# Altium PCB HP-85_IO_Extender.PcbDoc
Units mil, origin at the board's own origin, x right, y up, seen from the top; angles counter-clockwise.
Board outline 3937.01 x 3937.01 mil, 2 copper layers (Top Layer, Bottom Layer); 44 components, 33 nets, 145 pads, 56 vias.
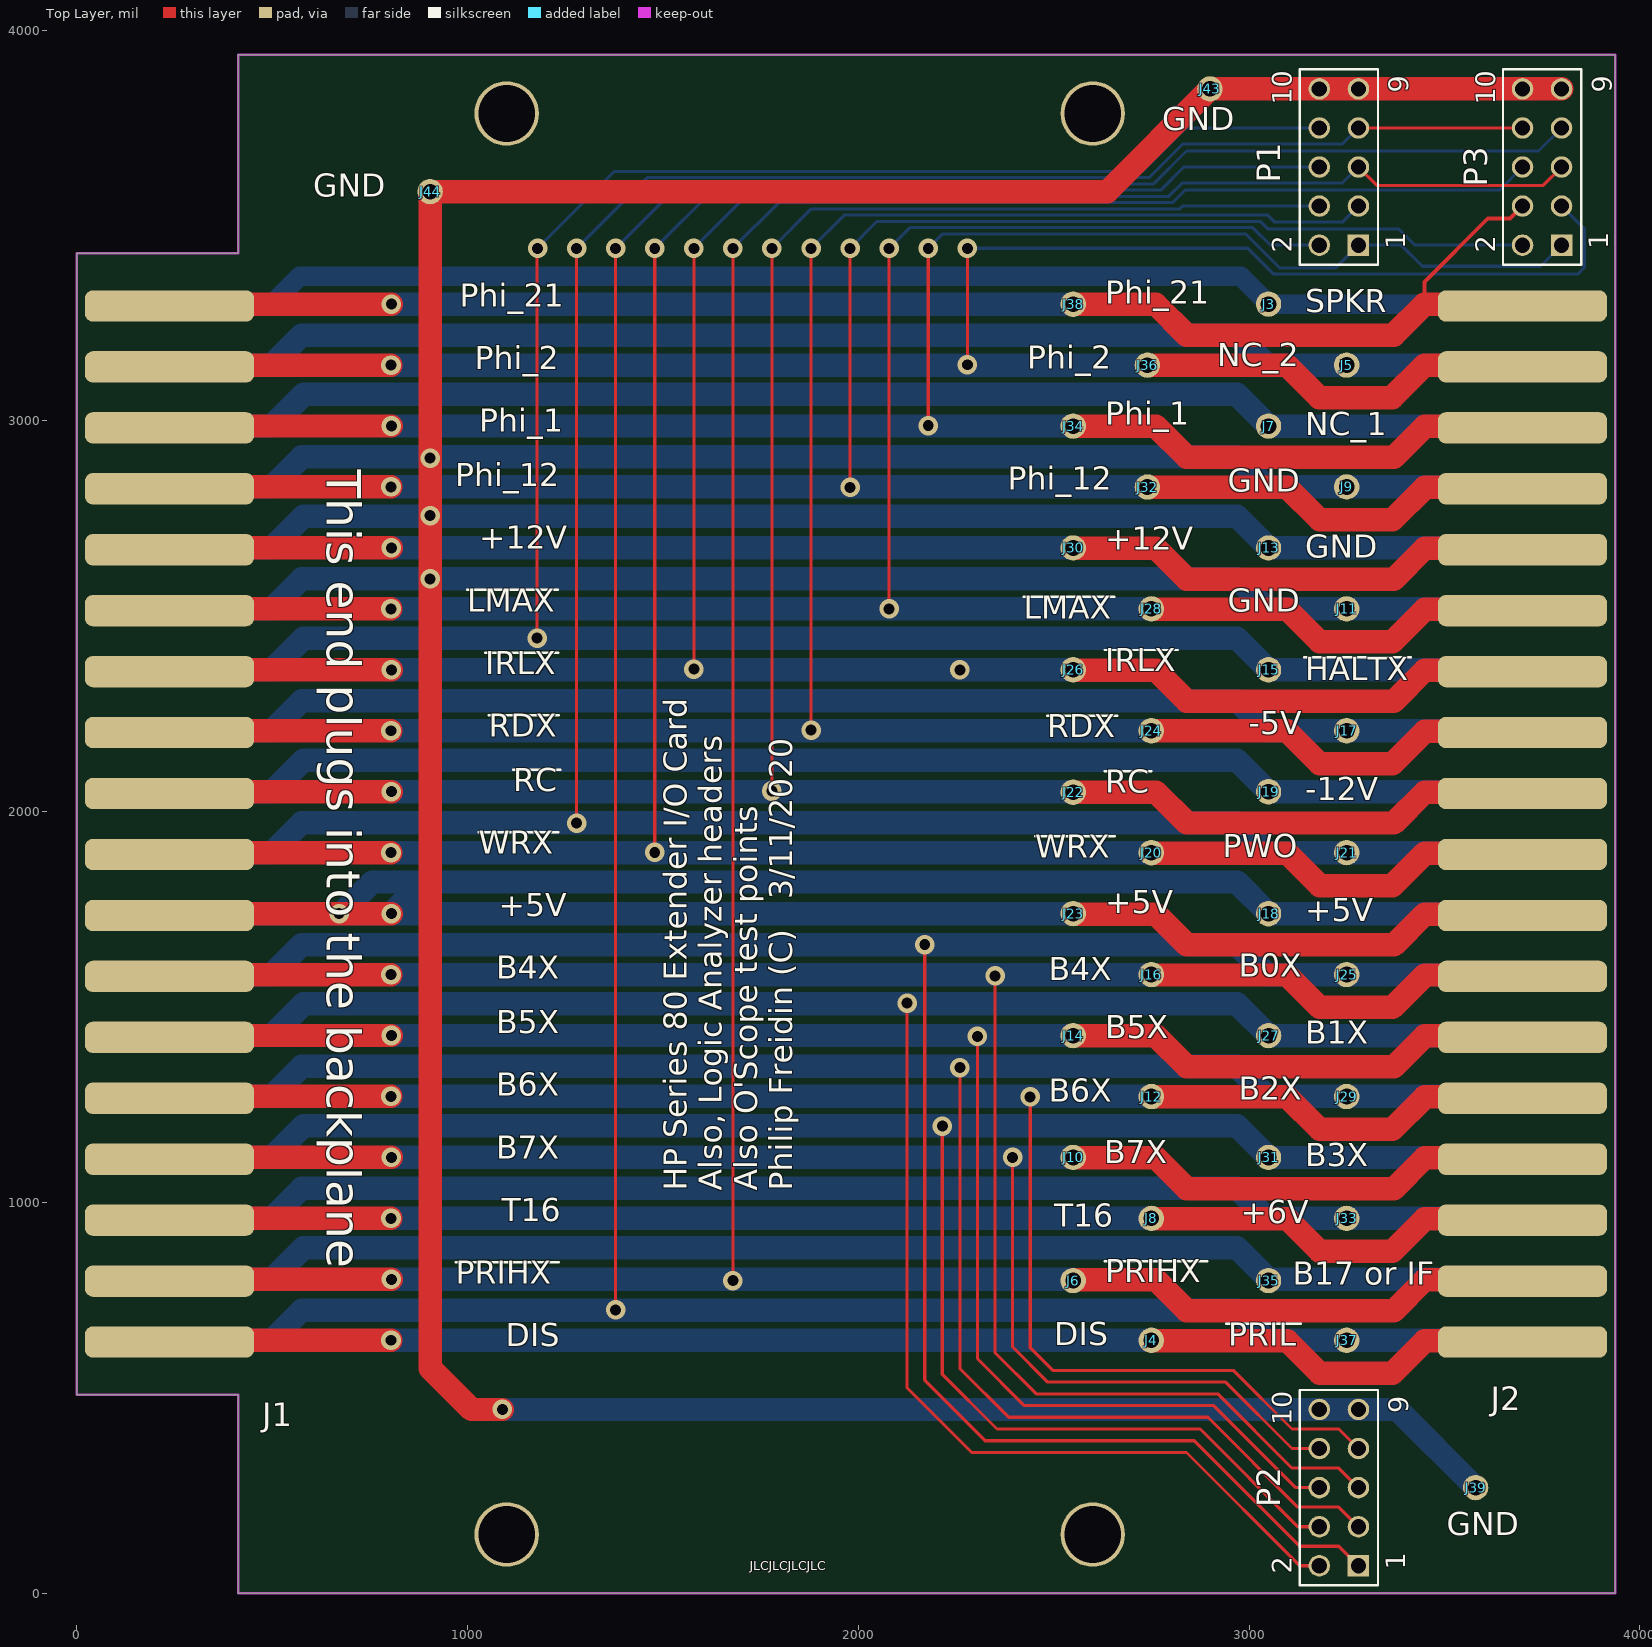
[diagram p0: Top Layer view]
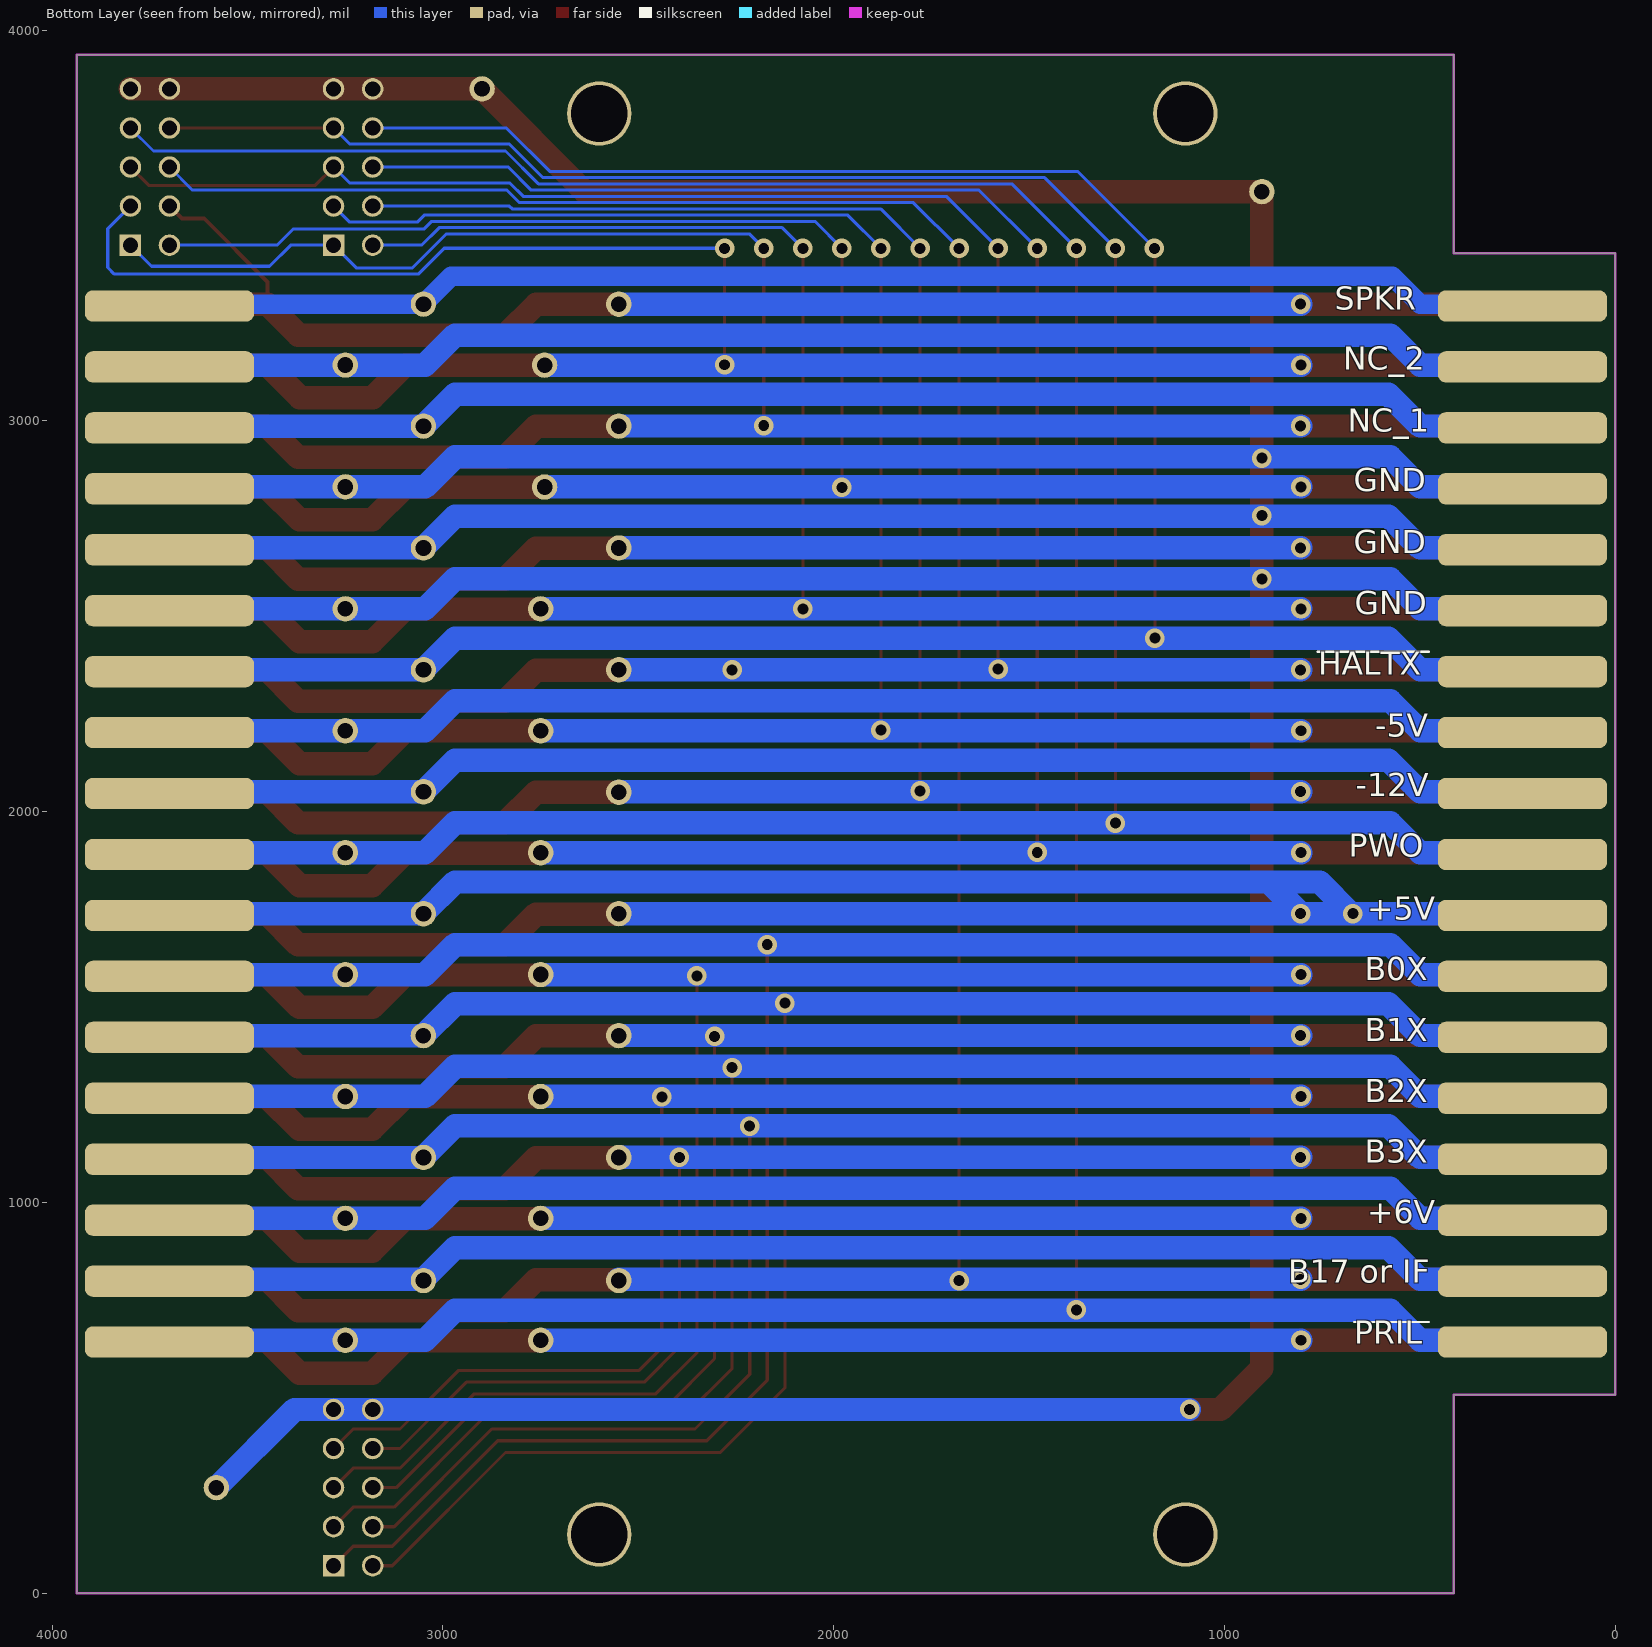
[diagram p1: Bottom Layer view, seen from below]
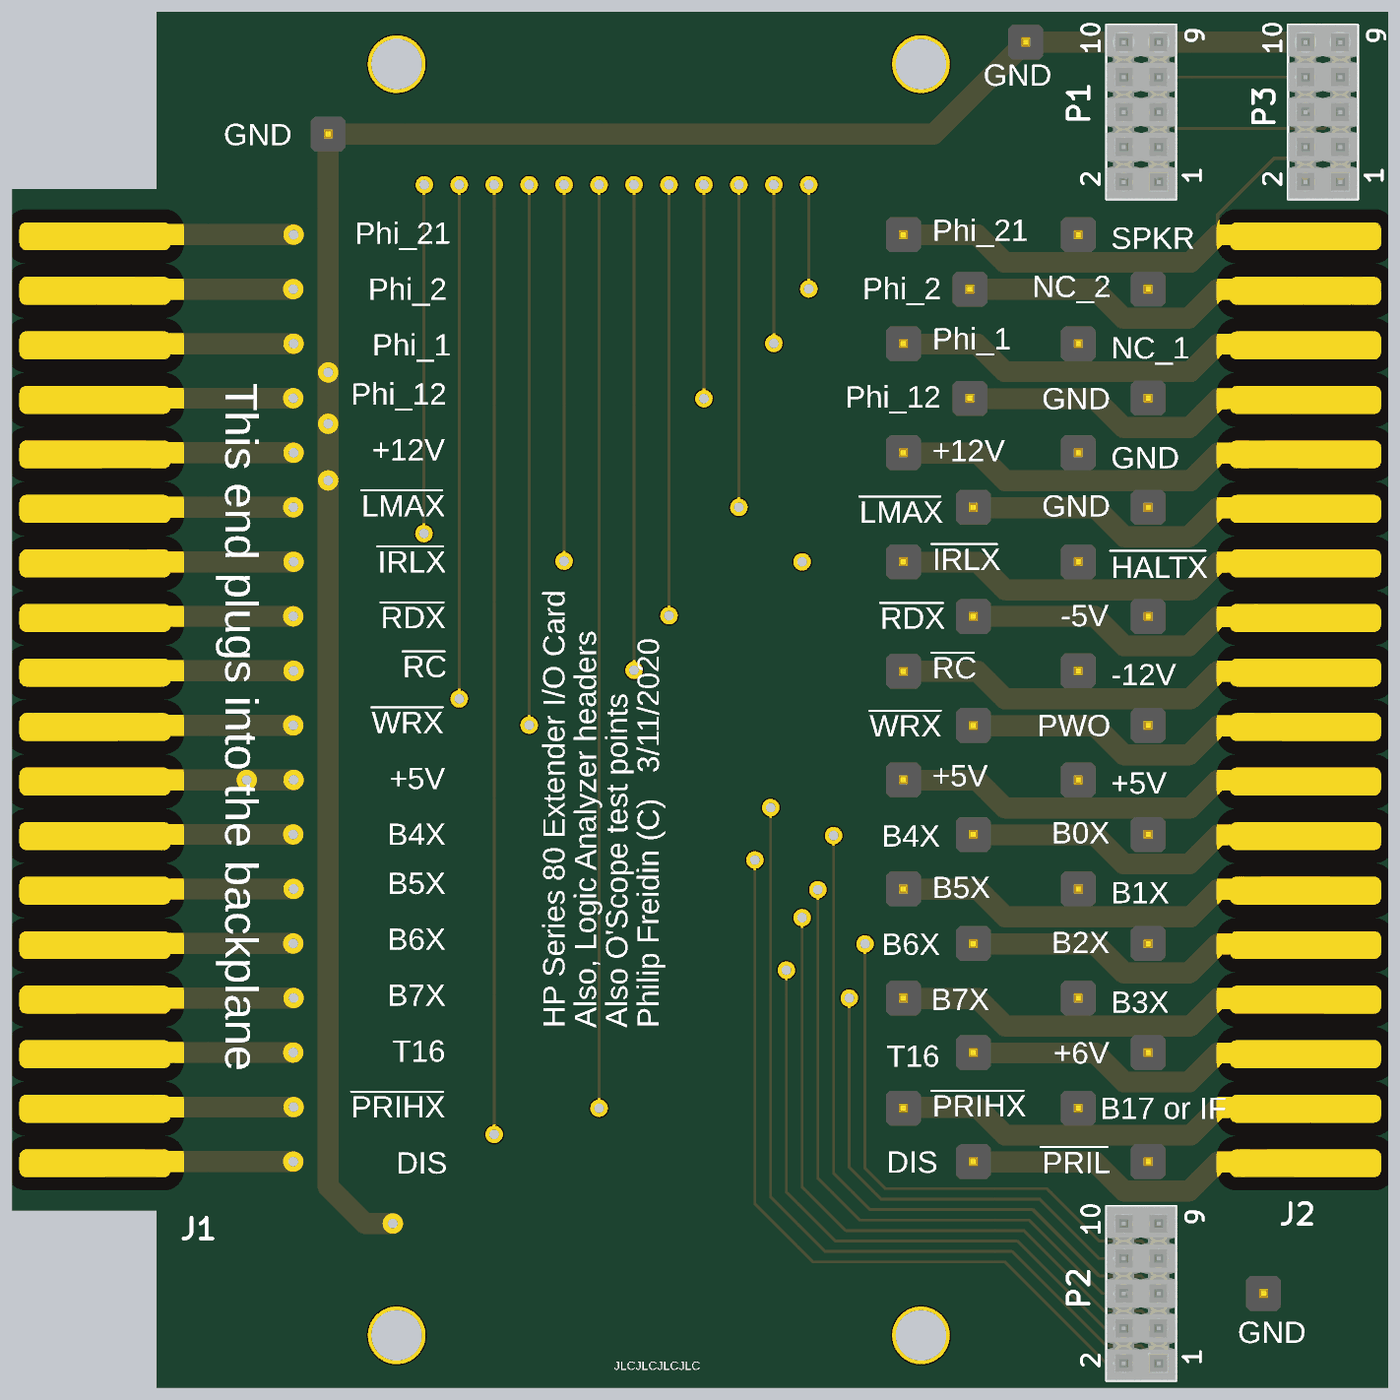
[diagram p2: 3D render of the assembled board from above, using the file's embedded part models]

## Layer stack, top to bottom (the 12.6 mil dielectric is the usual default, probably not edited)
Top Layer: signal copper 1.4
Dielectric: dielectric 12.6, FR-4, Dk 4.8
Bottom Layer: signal copper 1.4

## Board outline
0,507.87 0,3429.13 413.39,3429.13 413.39,3937.01 3937.01,3937.01 3937.01,0 413.39,0 413.39,507.87

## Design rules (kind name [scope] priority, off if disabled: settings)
Clearance [All] p1: gap=8
HoleSize [All] p1: absolutevalues=TRUE maxlimit=300 minlimit=10 maxpercent=80.000 minpercent=20.000
PolygonConnect [All] p1: connectstyle=Relief reliefconductorwidth=10 reliefentries=4 polygonreliefangle="90 Angle"
RoutingVias [All] p1: holewidth=28 width=50 viastyle="Through Hole" minholewidth=28 minwidth=50 maxholewidth=28 maxwidth=50
SilkToSilkClearance [All] p1: silktosilkclearance=3
SilkscreenOverComponentPads [All] p1: minsilkscreentomaskgap=10
SolderMaskExpansion [All] p1: expansion=4
Width [All] p1: maxlimit=100 minlimit=8 preferedwidth=20
25 further rules are at their usual default settings.

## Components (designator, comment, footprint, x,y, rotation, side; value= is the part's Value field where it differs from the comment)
J1 "Fingers for 36 pins 0.156\" pitch" "FINGERS FOR 36 PINS 0.156\" PITCH" 237.22,1968.5 r180 top
J2 "Fingers for 36 pins 0.156\" pitch" "FINGERS FOR 36 PINS 0.156\" PITCH" 3700,1968.5 r180 top
J3 "HDR 1X1" HDR_1X1_2MM54_ROUND 3050,3299.18 r0 top
J4 "HDR 1X1" HDR_1X1_2MM54_ROUND 2750,647 r0 top
J5 "HDR 1X1" HDR_1X1_2MM54_ROUND 3250,3143.18 r0 top
J6 "HDR 1X1" HDR_1X1_2MM54_ROUND 2550,800 r0 top
J7 "HDR 1X1" HDR_1X1_2MM54_ROUND 3050,2987 r0 top
J8 "HDR 1X1" HDR_1X1_2MM54_ROUND 2750,959 r0 top
J9 "HDR 1X1" HDR_1X1_2MM54_ROUND 3250,2831.18 r0 top
J10 "HDR 1X1" HDR_1X1_2MM54_ROUND 2550,1115 r0 top
J11 "HDR 1X1" HDR_1X1_2MM54_ROUND 3250,2519.18 r0 top
J12 "HDR 1X1" HDR_1X1_2MM54_ROUND 2750,1271 r0 top
J13 "HDR 1X1" HDR_1X1_2MM54_ROUND 3050,2675 r0 top
J14 "HDR 1X1" HDR_1X1_2MM54_ROUND 2550,1427 r0 top
J15 "HDR 1X1" HDR_1X1_2MM54_ROUND 3050,2363.18 r0 top
J16 "HDR 1X1" HDR_1X1_2MM54_ROUND 2750,1583.18 r0 top
J17 "HDR 1X1" HDR_1X1_2MM54_ROUND 3250,2207.18 r0 top
J18 "HDR 1X1" HDR_1X1_2MM54_ROUND 3050,1739 r0 top
J19 "HDR 1X1" HDR_1X1_2MM54_ROUND 3050,2051 r0 top
J20 "HDR 1X1" HDR_1X1_2MM54_ROUND 2750,1895 r90 top
J21 "HDR 1X1" HDR_1X1_2MM54_ROUND 3250,1895.18 r0 top
J22 "HDR 1X1" HDR_1X1_2MM54_ROUND 2550,2050 r90 top
J23 "HDR 1X1" HDR_1X1_2MM54_ROUND 2550,1739.18 r90 top
J24 "HDR 1X1" HDR_1X1_2MM54_ROUND 2750,2207.18 r90 top
J25 "HDR 1X1" HDR_1X1_2MM54_ROUND 3250,1583.18 r90 top
J26 "HDR 1X1" HDR_1X1_2MM54_ROUND 2550,2363.18 r90 top
J27 "HDR 1X1" HDR_1X1_2MM54_ROUND 3050.18,1427 r90 top
J28 "HDR 1X1" HDR_1X1_2MM54_ROUND 2750,2519.18 r90 top
J29 "HDR 1X1" HDR_1X1_2MM54_ROUND 3250,1271 r90 top
J30 "HDR 1X1" HDR_1X1_2MM54_ROUND 2550,2675 r90 top
J31 "HDR 1X1" HDR_1X1_2MM54_ROUND 3050,1115 r0 top
J32 "HDR 1X1" HDR_1X1_2MM54_ROUND 2740,2831 r90 top
J33 "HDR 1X1" HDR_1X1_2MM54_ROUND 3250,959.18 r90 top
J34 "HDR 1X1" HDR_1X1_2MM54_ROUND 2550,2987 r90 top
J35 "HDR 1X1" HDR_1X1_2MM54_ROUND 3050,800 r90 top
J36 "HDR 1X1" HDR_1X1_2MM54_ROUND 2740,3143 r90 top
J37 "HDR 1X1" HDR_1X1_2MM54_ROUND 3250,647 r90 top
J38 "HDR 1X1" HDR_1X1_2MM54_ROUND 2550,3299 r90 top
J39 "HDR 1X1" HDR_1X1_2MM54_ROUND 3580,270 r90 top
J43 "HDR 1X1" HDR_1X1_2MM54_ROUND 2900,3850 r90 top
J44 "HDR 1X1" HDR_1X1_2MM54_ROUND 904,3587 r90 top
P1 "Header 5X2" "HDR_5X2 alt 1" 3280,3450 r90 top
P2 "Header 5X2" "HDR_5X2 alt 1" 3280,70 r90 top
P3 "Header 5X2" "HDR_5X2 alt 1" 3800,3450 r90 top

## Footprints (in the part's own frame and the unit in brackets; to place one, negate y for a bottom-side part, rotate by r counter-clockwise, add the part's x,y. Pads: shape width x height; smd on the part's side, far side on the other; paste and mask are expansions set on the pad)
"FINGERS FOR 36 PINS 0.156\" PITCH" [mil] "PCB fingers to match 36 pin edge connector with 2x18 at 0.156\" pitch"
  rrect50% 433x80 smd far side paste-50 mask+38: B1(0,-1326) B2(0,-1170) B3(0,-1014) B4(0,-858) B5(0,-702) B6(0,-546) B7(0,-390) B8(0,-234) B9(0,-78) B10(0,78) B11(0,234) B12(0,390) B13(0,546) B14(0,702) B15(0,858) B16(0,1014) B17(0,1170) B18(0,1326)
  rrect50% 433x80 smd paste-50 mask+38: T1(0,-1326) T2(0,-1170) T3(0,-1014) T4(0,-858) T5(0,-702) T6(0,-546) T7(0,-390) T8(0,-234) T9(0,-78) T10(0,78) T11(0,234) T12(0,390) T13(0,546) T14(0,702) T15(0,858) T16(0,1014) T17(0,1170) T18(0,1326)
HDR_1X1_2MM54_ROUND [mil] "HDR_1X1_2MM54_02_11?2011"
  round 65 hole 40: 1(0,0)
  body extent -50,-50 50,50, height 398
"HDR_5X2 alt 1" [mil] "HDR_5X2_2MM54_2010/02/23"
  rect 55x55 hole 39: 1(0,0)
  round 55 hole 39: 2(0,100) 3(100,0) 4(100,100) 5(200,0) 6(200,100) 7(300,0) 8(300,100) 9(400,0) 10(400,100)
  silkscreen extent -50,-50 450,150, body extent -50,-50 450,150, height 330

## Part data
J1 J2: library part "J Fingers for 36 pins 0.156\" pitch for HP85", "Fingers for 36 pins 0.156\" pitch for HP85"
J3 J4 J5 J6 J7 J8 J9 J10 J11 J12 J13 J14 J15 J16 J17 J18 J19 J20 J21 J22 J23 J24 J25 J26 J27 J28 J29 J30 J31 J32 J33 J34 J35 J36 J37 J38 J39 J43 J44: library part "J Header 1X1", "Header, 1-Pin"
P1 P2 P3: library part "J Header 5X2", "Header, 5-Pin, Dual row"

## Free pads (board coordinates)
  round 165 hole 145: 0(1100,150) 0(1100,3787) 0(2600,150) 0(2600,3787)

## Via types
v1: diameter 50, hole 28, Top Layer to Bottom Layer, 56 vias

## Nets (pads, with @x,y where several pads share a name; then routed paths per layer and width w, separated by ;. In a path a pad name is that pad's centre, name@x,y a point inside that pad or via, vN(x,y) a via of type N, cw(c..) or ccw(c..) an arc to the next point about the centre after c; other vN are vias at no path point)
+5V: J1.B11 J1.T11 J2.B11 J2.T11 J18.1 J23.1 | length 7302.2
  Top Layer w60: J1.T11@237.22,1739.18 v1(805,1739.18) ; J23.1@2551,1738 2762,1738 2841,1659 3371,1659 3450,1738 J2.T11@3701,1738
  Bottom Layer w60: J1.B11@237.22,1739.18 v1(805,1739.18) ; v1@675,1739 756,1820 885.82,1820 ; J23.1@2549.82,1739.18 v1(805,1739.18) ; J2.B11@3700,1739 3050.18,1739 2969.18,1820 885.82,1820 ; v1(805,1739.18) 885.82,1820
  other v1: 671,1739
+6V: J1.B16 J2.B16 J33.1 | length 3526.2
  Bottom Layer w60: J1.B16@237.22,959.18 499,959.18 575.82,1036 2969.18,1036 3046,959.18 J33.1 J2.B16@3699.82,959.18
+12V: J1.T5 J2.T5 J30.1 | length 3528
  Top Layer w60: J1.T5@237.22,2675.18 v1(805,2675.18) ; J30.1@2551,2674 2762,2674 2841,2595 3371,2595 3450,2674 J2.T5@3701,2674
  Bottom Layer w60: v1(805,2675.18) J30.1@2549.82,2675.18
-5V: J1.B8 J2.B8 J17.1 | length 3526.2
  Bottom Layer w60: J1.B8@237.22,2207.18 499,2207.18 575.82,2284 2969.18,2284 3046,2207.18 J17.1 J2.B8@3699.82,2207.18
-12V: J1.B9 J2.B9 J19.1 | length 3529.8
  Bottom Layer w60: J1.B9@237.22,2051.18 499.18,2051.18 580,2132 2969.18,2132 3050,2051.18 3050.18,2051 J2.B9@3700,2051
\HALTX: J1.B7 J2.B7 J15.1 P1.8 | length 6656.8
  Top Layer w8: v1(1178,2444) 1178,3441 v1(1179,3442)
  Bottom Layer w8: v1(1179,3442) 1376,3639 2727,3639 2838,3750 P1.8
  Bottom Layer w60: J1.B7@237.22,2363.18 499.18,2363.18 580,2444 v1(1178,2444) 2969.18,2444 J15.1 3050.18,2363 J2.B7@3700,2363
\IRLX: J1.T7 J2.T7 J26.1 P1.5 P3.5 | length 6951.1
  Top Layer w8: v1(1579,2365) v1(1579,3442) ; P1.5 3327,3603 3753,3603 P3.5
  Top Layer w60: J1.T7@237.22,2363.18 v1(805,2363.18) ; J26.1@2551,2362 2762,2362 2841,2283 3371,2283 3450,2362 J2.T7@3701,2362
  Bottom Layer w8: v1(1579,3442) 1712,3575 2795,3575 2829,3609 3239,3609 P1.5
  Bottom Layer w60: v1(805,2363.18) J26.1@2549.82,2363.18
  other v1: 2260,2363
\LMAX: J1.T6 J2.T6 J28.1 P1.2 | length 5587
  Top Layer w8: v1(2079,2519) v1(2079,3442)
  Top Layer w60: J1.T6@237.22,2519.18 v1(804,2519.18) ; J28.1@2750,2518 3098,2518 3181,2435 3367.18,2435 3450.18,2518 J2.T6@3701,2518
  Bottom Layer w8: v1(2079,3442) 2132,3495 3010,3495 3055,3450 P1.2
  Bottom Layer w60: v1(804,2519.18) J28.1@2739.82,2519.18
\PRIHX: J1.T17 J2.T17 J6.1 P3.6 | length 8277.2
  Top Layer w8: v1(1679,800) v1(1679,3442)
  Top Layer w60: J1.T17@237.22,803.18 v1(805,803.18) ; J6.1@2551,802 2762,802 2841,723 3371,723 3450,802 J2.T17@3701,802
  Bottom Layer w8: v1(1679,3442) 1796,3559 2804,3559 2836,3591 3641,3591 P3.6
  Bottom Layer w60: v1(805,803.18) J6.1@2549.82,803.18
\PRIL: J1.B18 J2.B18 J37.1 P3.7 | length 8791.8
  Top Layer w8: v1(1379,725) v1(1379,3442)
  Bottom Layer w8: v1(1379,3442) 1544,3607 2756,3607 2840,3691 3741,3691 P3.7
  Bottom Layer w60: J1.B18@237.22,647.18 499,647.18 575.82,724 2969.18,724 3046,647.18 J2.B18@3699.82,647.18
\RC: J1.T9 J2.T9 J22.1 P1.4 | length 6363.8
  Top Layer w8: v1(1779,2053) v1(1779,3442) ; J22.1 J22.1@2551,2050
  Top Layer w60: J1.T9@237.22,2051.18 v1(805,2051.18) ; J22.1@2551,2050 2762,2050 2841,1971 3371,1971 3450,2050 J2.T9@3701,2050
  Bottom Layer w8: v1(1779,3442) 1880,3543 2823,3543 2830,3550 P1.4
  Bottom Layer w60: v1(805,2051.18) J22.1@2549.82,2051.18
\RDX: J1.T8 J2.T8 J24.1 P1.3 | length 6216.5
  Top Layer w8: v1(1879,2209) v1(1879,3442)
  Top Layer w60: J1.T8@237.22,2207.18 v1(804,2207.18) ; J24.1 3096.82,2207.18 3181,2123 3367.18,2123 3450.18,2206 J2.T8@3701,2206
  Bottom Layer w8: v1(1879,3442) 1964,3527 3048,3527 3066,3509 3239,3509 P1.3
  Bottom Layer w60: v1(804,2207.18) J24.1@2739.82,2207.18
\WRX: J1.T10 J2.T10 J20.1 P1.6 | length 6855.5
  Top Layer w8: v1(1479,1896) v1(1479,3442)
  Top Layer w60: J1.T10@237.22,1895.18 v1(804,1895.18) ; J20.1@2750,1894 3098,1894 3181,1811 3367.18,1811 3450.18,1894 J2.T10@3701,1894
  Bottom Layer w8: v1(1479,3442) 1628,3591 2774,3591 2833,3650 P1.6
  Bottom Layer w60: v1(804,1895.18) J20.1@2739.82,1895.18
B0X: J1.B12 J2.B12 J25.1 P2.1 | length 5948
  Top Layer w8: v1(2170,1660) 2170,545 2325,390 2860,390 3130,120 3230,120 P2.1
  Bottom Layer w60: J1.B12@237.22,1583.18 499,1583.18 575.82,1660 2969.18,1660 3046,1583.18 J25.1 J2.B12@3699.82,1583.18
B1X: J1.B13 J2.B13 J27.1 P2.2 | length 5758.3
  Top Layer w8: v1(2125,1510) 2125,525 2290,360 2840,360 3130,70 P2.2
  Bottom Layer w60: J1.B13@237.22,1427.18 499.18,1427.18 580,1508 2969.18,1508 J27.1 J2.B13@3700,1427
B2X: J1.B14 J2.B14 J29.1 P2.3 | length 5484
  Top Layer w8: v1(2260,1345) 2260,575 2385,450 2895,450 3125,220 3230,220 P2.3
  Bottom Layer w60: J1.B14@237.22,1271.18 499,1271.18 575.82,1348 2969.18,1348 3046,1271.18 J2.B14@3699.82,1271.18
B3X: J1.B15 J2.B15 J31.1 P2.4 | length 5291.4
  Top Layer w8: v1(2215,1195) 2215,560 2355,420 2875,420 3125,170 P2.4
  Bottom Layer w60: J1.B15@237.22,1115.18 499.18,1115.18 580,1196 2969.18,1196 3050.18,1115 J2.B15@3700,1115
B4X: J1.T12 J2.T12 J16.1 P2.5 | length 5560.3
  Top Layer w8: v1(2350,1580) 2350,615 2455,510 2920,510 3110,320 3230,320 P2.5
  Top Layer w60: J1.T12@237.22,1583.18 v1(804,1583.18) ; J16.1@2750,1582 3098,1582 3181,1499 3367.18,1499 3450.18,1582 J2.T12@3701,1582
  Bottom Layer w60: v1(804,1583.18) J16.1@2739.82,1583.18
B5X: J1.T13 J2.T13 J14.1 P2.6 | length 5364.7
  Top Layer w8: v1(2305,1425) 2305,600 2425,480 2910,480 3120,270 P2.6
  Top Layer w60: J1.T13@237.22,1427.18 v1(805,1427.18) ; J14.1@2551,1426 2762,1426 2841,1347 3371,1347 3450,1426 J2.T13@3701,1426
  Bottom Layer w60: v1(805,1427.18) J14.1@2549.82,1427.18
B6X: J1.T14 J2.T14 J12.1 P2.7 | length 5111.2
  Top Layer w8: v1(2440,1270) 2440,628 2498,570 2960,570 3110,420 3230,420 P2.7
  Top Layer w60: J1.T14@237.22,1271.18 v1(804,1271.18) ; J12.1@2750,1270 3098,1270 3181,1187 3367.18,1187 3450.18,1270 J2.T14@3701,1270
  Bottom Layer w60: v1(804,1271.18) J12.1@2739.82,1271.18
B7X: J1.T15 J2.T15 J10.1 P2.8 | length 4905.7
  Top Layer w8: v1(2395,1115) 2395,630 2485,540 2940,540 3110,370 P2.8
  Top Layer w60: J1.T15@237.22,1115.18 v1(805,1115.18) ; J10.1@2551,1114 2762,1114 2841,1035 3371,1035 3450,1114 J2.T15@3701,1114
  Bottom Layer w60: v1(805,1115.18) J10.1@2549.82,1115.18
B17: J1.B17 J2.B17 J35.1 | length 3529.8
  Bottom Layer w60: J1.B17@237.22,803.18 499.18,803.18 580,884 2969.18,884 3050,803.18 3050.18,803 J2.B17@3700,803
DIS: J1.T18 J2.T18 J4.1 | length 3522.4
  Top Layer w60: J1.T18@237.22,647.18 v1(804,647.18) ; J4.1@2750,646 3098,646 3181,563 3367.18,563 3450.18,646 J2.T18@3701,646
  Bottom Layer w60: v1(804,647.18) J4.1@2739.82,647.18
GND: J1.B4 J1.B5 J1.B6 J2.B4 J2.B5 J2.B6 J9.1 J11.1 J13.1 J39.1 J43.1 J44.1 P1.9 P1.10 P2.9 P2.10 P3.9 P3.10 | length 19400
  Top Layer w60: v1(1089,470) 1010,470 904,576 v1(904,2596) v1(904,2758) v1(904,2905) J44.1 2637,3587 J43.1 P1.10 P1.9 P3.10 P3.9
  Bottom Layer w60: J1.B6@237.22,2519.18 499,2519.18 575.82,2596 v1(904,2596) 2969.18,2596 3046,2519.18 J11.1 J2.B6@3699.82,2519.18 ; J1.B5@237.22,2675.18 499.18,2675.18 580,2756 2969.18,2756 3050.18,2675 J2.B5@3700,2675 ; J1.B4@237.22,2831.18 499,2831.18 575.82,2908 2969.18,2908 3046,2831.18 J9.1 J2.B4@3699.82,2831.18 ; v1@1090,470 P2.10 P2.9 3380,470 J39.1
NC_1: J1.B3 J2.B3 J7.1 | length 3529.8
  Bottom Layer w60: J1.B3@237.22,2987.18 499.18,2987.18 580,3068 2969.18,3068 3050,2987.18 3050.18,2987 J2.B3@3700,2987
NC_2: J1.B2 J2.B2 J5.1 | length 3526.2
  Bottom Layer w60: J1.B2@237.22,3143.18 499,3143.18 575.82,3220 2969.18,3220 3046,3143.18 J5.1 J2.B2@3699.82,3143.18
PHI_1: J1.T3 J2.T3 J34.1 P1.1 P3.1 | length 5724.6
  Top Layer w8: v1(2179,2988) v1(2179,3442) ; J34.1 J34.1@2551,2986
  Top Layer w60: J1.T3@237.22,2987.18 v1(805,2987.18) ; J34.1@2551,2986 2762,2986 2841,2907 3371,2907 3450,2986 J2.T3@3701,2986
  Bottom Layer w8: v1(2179,3442) 2216,3479 2991,3479 3078,3392 3222,3392 P1.1 3390,3450 3444,3396 3746,3396 P3.1
  Bottom Layer w60: v1(805,2987.18) J34.1@2549.82,2987.18
PHI_2: J1.T2 J2.T2 J36.1 P3.3 | length 5623.8
  Top Layer w8: v1(2279,3144) v1(2279,3442)
  Top Layer w60: J1.T2@237.22,3143.18 v1(804,3143.18) ; J36.1 3097,3143 3180,3060 3366.18,3060 3449.18,3143 J2.T2@3700,3143
  Bottom Layer w8: v1(2279,3442) 2997,3442 3063,3376 3841,3376 3858,3393 3858,3492 P3.3
  Bottom Layer w60: v1(804,3143.18) J36.1@2739.82,3143.18
PHI_12: J1.T4 J2.T4 J32.1 P3.2 | length 5918.2
  Top Layer w8: v1(1979,2830) v1(1979,3442)
  Top Layer w60: J1.T4@237.22,2831.18 v1(804,2831.18) ; J32.1@2741,2830 3098,2830 3181,2747 3367.18,2747 3450.18,2830 J2.T4@3701,2830
  Bottom Layer w8: v1(1979,3442) 2048,3511 3029,3511 3049,3491 3384,3491 3425,3450 P3.2
  Bottom Layer w60: v1(804,2831.18) J32.1@2739.82,2831.18
PHI_21: J1.T1 J2.T1 J38.1 P3.4 | length 3916.7
  Top Layer w10: 3449,3299 3449,3356 3611,3518 3668,3518 P3.4
  Top Layer w60: J1.T1@237.22,3299.18 v1(805,3299.18) ; J38.1 2761,3299 2840,3220 3370,3220 3449,3299 J2.T1@3700,3299
  Bottom Layer w60: v1(805,3299.18) 2549.82,3299.18 J38.1
PWO: J1.B10 J2.B10 J21.1 P1.7 P3.8 | length 7545.8
  Top Layer w8: v1(1279,1971) v1(1279,3442) ; P1.7 P3.8
  Bottom Layer w8: v1(1279,3442) 1460,3623 2744,3623 2830,3709 3239,3709 P1.7
  Bottom Layer w60: J1.B10@237.22,1895.18 499,1895.18 575.82,1972 2969.18,1972 3046,1895.18 J21.1 J2.B10@3699.82,1895.18
SPKR: J1.B1 J2.B1 J3.1 | length 3521.5
  Bottom Layer w50: J1.B1@237.22,3299.18 499.18,3299.18 570,3370 2979.18,3370 J3.1 ; J3.1@3050.18,3299 J2.B1@3700,3299
  Bottom Layer w60: J3.1 J3.1@3050.18,3299
T16: J1.T16 J2.T16 J8.1 | length 3522.4
  Top Layer w60: J1.T16@237.22,959.18 v1(804,959.18) ; J8.1@2750,958 3098,958 3181,875 3367.18,875 3450.18,958 J2.T16@3701,958
  Bottom Layer w60: v1(804,959.18) J8.1@2739.82,959.18

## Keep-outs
Keep-Out Layer:
  the board outline again, w6

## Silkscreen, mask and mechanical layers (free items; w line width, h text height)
Top Overlay:
  lines w6: 970,847 1233,847 ; 999,2568 1230.37,2568 ; 1028,1947 1232,1947 ; 1045,2407 1232,2407 ; 1054,2247 1234,2247 ; 1117,2107 1237,2107 ; 2423.73,2549.87 2655.1,2549.87 ; 2452.73,1937.32 2656.73,1937.32 ; 2482.96,2245.77 2662.96,2245.77 ; 2630.21,849.74 2893.21,849.74 ; 2630.21,2103.4 2750.21,2103.4 ; 2630.21,2413.96 2817.21,2413.96 ; 2941.89,689.19 3132.92,689.19 ; 3141.55,2395 3413.72,2395
  text "GND" at 2778.38,3725.34 h100
  text "GND" at 604.72,3555.22 h100
  text "Phi_21" at 2632.21,3281.19 h100
  text "Phi_21" at 980.25,3273.16 h100
  text "SPKR" at 3143.55,3258.81 h100
  text "NC_2" at 2918.2,3120.73 h100
  text "Phi_2" at 2432.42,3114.77 h100
  text "Phi_2" at 1018.27,3113.16 h100
  text "Phi_1" at 2632.21,2971.19 h100
  text "Phi_1" at 1030.02,2953.16 h100
  text "NC_1" at 3143.55,2944.81 h100
  text "Phi_12" at 968.5,2813.16 h100
  text "Phi_12" at 2382.66,2804.77 h100
  text "GND" at 2946.04,2799.73 h100
  text "+12V" at 1029.65,2653.16 h100
  text "+12V" at 2632.21,2651.19 h100
  text "GND" at 3143.55,2630.81 h100
  text "LMAX" at 999.03,2493.16 h100
  text "GND" at 2946.04,2492.73 h100
  text "LMAX" at 2423.76,2475.03 h100
  text "IRLX" at 2632.21,2340.13 h100
  text "IRLX" at 1045.56,2333.16 h100
  text "HALTX" at 3143.55,2316.74 h100
  text "-5V" at 2999.6,2178.73 h100
  text "RDX" at 1054.34,2173.16 h100
  text "RDX" at 2483.3,2171.93 h100
  text "RC" at 1116.87,2033.16 h100
  text "RC" at 2632.21,2029.56 h100
  text "-12V" at 3143.55,2009.81 h100
  text "WRX" at 1028.44,1873.16 h100
  text "PWO" at 2932.53,1864.73 h100
  text "WRX" at 2453.17,1863.48 h100
  text "+5V" at 2632.21,1721.19 h100
  text "+5V" at 1079.41,1713.16 h100
  text "+5V" at 3143.55,1699.81 h100
  text "B0X" at 2973.42,1557.73 h100
  text "B4X" at 1073.58,1553.16 h100
  text "B4X" at 2487.74,1548.77 h100
  text "B5X" at 1073.58,1413.16 h100
  text "B5X" at 2632.21,1401.19 h100
  text "B1X" at 3143.55,1386.81 h100
  text "B6X" at 1073.58,1253.16 h100
  text "B2X" at 2973.42,1243.73 h100
  text "B6X" at 2487.74,1238.77 h100
  text "B7X" at 1073.58,1093.16 h100
  text "B7X" at 2629,1081.17 h100
  text "B3X" at 3143.55,1072.81 h100
  text "HP Series 80 Extender I/O Card" at 1580,1030 h100 r90
  text "Also, Logic Analyzer headers" at 1670,1030 h100 r90
  text "Also O'Scope test points" at 1760,1030 h100 r90
  text "Philip Freidin (C)   3/11/2020" at 1850,1030 h100 r90
  text "T16" at 1087.46,933.16 h100
  text "+6V" at 2979.25,927.73 h100
  text "T16" at 2501.61,918.77 h100
  text "PRIHX" at 2632.21,775.9 h100
  text "PRIHX" at 969.71,773.16 h100
  text "B17 or IF" at 3112.07,769.76 h100
  text "DIS" at 2501.41,615.42 h100
  text "PRIL" at 2946.5,614.12 h100
  text "DIS" at 1098,613.16 h100
  text "GND" at 3506.08,128.41 h100
  text "JLCJLCJLCJLC" at 1721.7,51.41 h39.37
Bottom Overlay:
  lines w6: 476.77,693.96 667.8,693.96 ; 477.03,2409.67 761.62,2409.69
  text "SPKR" at 717.36,3265.78 h100
  text "NC_2" at 695.36,3111.78 h100
  text "NC_1" at 684.36,2953.78 h100
  text "GND" at 668.36,2800.78 h100
  text "GND" at 668.36,2642.78 h100
  text "GND" at 666.36,2485.78 h100
  text "HALTX" at 759.36,2331.78 h100
  text "-5V" at 614.36,2172.78 h100
  text "-12V" at 664.36,2019.78 h100
  text "PWO" at 681.36,1865.78 h100
  text "+5V" at 634.82,1704.58 h100
  text "B0X" at 640.36,1549.78 h100
  text "B1X" at 640.36,1393.78 h100
  text "B2X" at 640.36,1237.78 h100
  text "B3X" at 640.36,1081.78 h100
  text "+6V" at 634.36,927.78 h100
  text "B17 or IF" at 836.19,774.53 h100
  text "PRIL" at 667.56,618.88 h100
Mechanical 1:
  circle w1: c2600,150 r72.5
  circle w1: c1100,150 r72.5
  circle w1: c2600,3787 r72.5
  circle w1: c1100,3787 r72.5

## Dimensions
0,3429.13 to 3937.01,3937.01 on Mechanical 1
0,507.87 to 0,0 on Mechanical 1
0,3429.13 to 0,507.87 on Mechanical 1
1100,3787 to 1391.92,4068.38 on Mechanical 1
0,3429.13 to 413.39,3937.01 on Mechanical 1
413.39,3937.01 to 413.39,0 on Mechanical 1
413.39,0 to 1100,150 on Mechanical 1
0,0 to 2600,150 on Mechanical 1
0,0 to 1100,150 on Mechanical 1
1100,3787 to 413.39,3937.01 on Mechanical 1
413.39,3937.01 to 0,3429.13 on Mechanical 1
